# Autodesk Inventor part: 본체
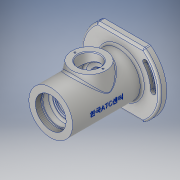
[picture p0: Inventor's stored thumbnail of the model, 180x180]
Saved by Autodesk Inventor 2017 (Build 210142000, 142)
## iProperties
Part Number: 본체
Material: 알루미늄 6061
Document SubType Name: Modeling
Designer: Administrator
Density: 2.7 g/cm^3
Appearance: 알루미늄 - 평지
Mass: 690.714 g
Surface Area: 618.652 cm^2
Volume: 255.82 cm^3
Author: Administrator
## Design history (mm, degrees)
sketch "스케치1"
  geometry: L1 (-33.985, 47)-(33.985, 47); L2 (33.985, 47)-(33.985, -47); L3 (33.985, -47)-(-33.985, -47); L4 (-33.985, -47)-(-33.985, 47); L5 (-33.985, 47)-(33.985, -47); L6 (33.985, 47)-(-33.985, -47); A1 r 58 centre (0, 0) between (-33.985, 47) and (-33.985, -47); A2 r 58 centre (0, 0) between (33.985, 47) and (-33.985, 47); A3 r 58 centre (0, 0) between (-33.985, -47) and (33.985, 47); 1 further point
  constraints: 12 end point, 8 point on circle, 3 centre point, 2 midpoint, 2 parallel, 1 coincident, 1 horizontal, 1 perpendicular
  dimensions: "d0" = 116 diameter of A1; "d1" = 94 distance of L3.end L1.start
extrude "돌출1" new body sketch "스케치1" distance "d2" = 10; taper "d3" = 0 deg
sketch "스케치2"
  geometry: C1 r 36 at (0, 0); 1 further point
  constraints: 1 centre point, 1 coincident
  dimensions: "d4" = 72 diameter of C1
extrude "돌출2" join sketch "스케치2" distance "d5" = 3; taper "d6" = 0 deg
sketch "스케치3"
  geometry: C1 r 32 at (0, 0); 1 further point
  constraints: 1 centre point, 1 coincident
  dimensions: "d7" = 64 diameter of C1
extrude "돌출3" join sketch "스케치3" distance "d8" = 102; taper "d9" = 0 deg
sketch "스케치4"
  geometry: L1 (0, 0)-(48, 0); L2 (0, 0)-(36.77, 30.854); L3 (-48, 0)-(0, 0); L4 (-36.77, -30.854)-(0, 0); C1 r 4 at (-36.77, -30.854); C2 r 4 at (36.77, 30.854); A1 r 48 centre (0, 0) between (48, 0) and (36.77, 30.854); A2 r 48 centre (0, 0) between (48, 0) and (36.77, 30.854); A3 r 48 centre (0, 0) between (-48, 0) and (-36.77, -30.854); 1 further point
  constraints: 8 end point, 8 point on circle, 5 centre point, 3 coincident, 2 concentric, 2 horizontal alignment
  dimensions: "d10" = 96 diameter of A1; "d11" = 40 deg angle of L1 L2; "d13" = 40 deg angle of L4 L3; "d15" = 8 diameter of C1; "d16" = 8 diameter of C2
extrude "돌출4" cut sketch "스케치4" distance "d17" = 10; taper "d18" = 0 deg
sketch "스케치5"
  geometry: L1 (-48, 0)-(48, 0); L2 (-36.77, -30.854)-(36.77, 30.854); C1 r 4 at (-36.77, -30.854) reference; C2 r 4 at (36.77, 30.854) reference; A1 r 48 centre (0, 0) between (-48, 0) and (48, 0); A2 r 48 centre (0, 0) between (48, 0) and (36.77, 30.854); A3 r 52 centre (0, 0) between (52, 0) and (39.834, 33.425); A4 r 44 centre (0, 0) between (44, 0) and (33.706, 28.283); A5 r 4 centre (48, 0) between (44, 0) and (52, 0); A6 r 4 centre (36.77, 30.854) between (39.834, 33.425) and (33.706, 28.283); A7 r 48 centre (0, 0) between (-48, 0) and (-36.77, -30.854); A8 r 52 centre (0, 0) between (-52, 0) and (-39.834, -33.425); A9 r 44 centre (0, 0) between (-44, 0) and (-33.706, -28.283); A10 r 4 centre (-48, 0) between (-44, 0) and (-52, 0); A11 r 4 centre (-36.77, -30.854) between (-39.834, -33.425) and (-33.706, -28.283); 2 further points
  constraints: 22 point on circle, 11 centre point, 8 tangent, 4 end point, 2 concentric, 2 horizontal alignment, 1 coincident, 1 horizontal, 1 midpoint
  dimensions: "d19" = 96 diameter of A1; "d20" = 8 diameter of A5; "d21" = 8 diameter of A10; "d22" = 30.85381 vertical distance of L2.start L1.start
extrude "돌출5" cut sketch "스케치5" distance "d23" = 4.4; taper "d24" = 0 deg
sketch "스케치6" dims "d25" = 96
  geometry: L1 (-36.77, -30.854)-(0, 0); L2 (0, 0)-(36.77, 30.854); L3 (0, 0)-(-48, 0); L4 (0, 0)-(48, 0); C1 r 4 at (-36.77, -30.854) reference; C2 r 4 at (36.77, 30.854) reference; A1 r 4 centre (48, 0) between (44, 0) and (52, 0) reference; A2 r 48 centre (0, 0) between (-48, 0) and (-36.77, -30.854); A3 r 50.25 centre (0, 0) between (-50.25, 0) and (-38.494, -32.3); A4 r 45.75 centre (0, 0) between (-45.75, 0) and (-35.047, -29.408); A5 r 2.25 centre (-48, 0) between (-45.75, 0) and (-50.25, 0); A6 r 2.25 centre (-36.77, -30.854) between (-38.494, -32.3) and (-35.047, -29.408); A7 r 48 centre (0, 0) between (48, 0) and (36.77, 30.854); A8 r 50.25 centre (0, 0) between (50.25, 0) and (38.494, 32.3); A9 r 45.75 centre (0, 0) between (45.75, 0) and (35.047, 29.408); A10 r 2.25 centre (48, 0) between (45.75, 0) and (50.25, 0); A11 r 2.25 centre (36.77, 30.854) between (38.494, 32.3) and (35.047, 29.408); 1 further point
  constraints: 20 point on circle, 10 centre point, 8 end point, 8 tangent, 2 horizontal, 1 coincident, 1 collinear, 1 concentric, 1 horizontal alignment, 3 other
  dimensions: "d26" = 4.5 diameter of A5; "d27" = 4.5 diameter of A10
extrude "돌출6" cut sketch "스케치6" distance "d28" = 10; taper "d29" = 0 deg
sketch "스케치7"
  geometry: L1 (32, 112)-(-32, 112) reference; L2 (0, 112)-(0, -3); L3 (-36, -3)-(36, -3) reference; L4 (0, 112)-(22.5, 112); L5 (22.5, 112)-(22.5, 104); L6 (22.5, 104)-(24, 104); L7 (24, 104)-(24, 101); L8 (24, 101)-(22.5, 101); L9 (22.5, 101)-(22.5, 90); L10 (22.5, 90)-(17.5, 90); L11 (17.5, 90)-(17.5, 88.25); L12 (17.5, 88.25)-(18.5, 88.25); L13 (18.5, 88.25)-(18.5, 86); L14 (18.5, 86)-(17.5, 86); L15 (17.5, 86)-(17.5, 75); L16 (17.5, 75)-(27, 75); L17 (27, 75)-(27, 37); L18 (27, 37)-(17.5, 37); L19 (17.5, 37)-(17.5, 26); L20 (17.5, 26)-(15, 26); L21 (15, 26)-(15, 21); L22 (15, 21)-(11, 21); L23 (11, 21)-(11, 18.3); L24 (11, 18.3)-(15, 18.3); L25 (15, 18.3)-(15, 11); L26 (15, 11)-(20, 11); L27 (20, 11)-(30, -3); 1 further point
  constraints: 50 end point, 19 perpendicular, 4 point on line, 2 midpoint, 1 horizontal, 1 vertical
  dimensions: "d30" = 45 diameter of L5 L2; "d31" = 48 diameter of L7 L2; "d32" = 45 diameter of L9 L2; "d33" = 35 diameter of L11 L2; "d34" = 37 diameter of L13 L2; "d35" = 54 diameter of L17 L2; "d36" = 35 diameter of L19 L2; "d37" = 30 diameter of L21 L2; "d38" = 22 diameter of L23 L2; "d39" = 30 diameter of L25 L2; "d41" = 40 diameter of L26.end L2; "d42" = 60 diameter of L27.end L2; "d43" = 8 distance of L4.end L5.end; "d44" = 3 distance of L6.end L7.end; "d45" = 22 distance between parallel lines of L10 L4; "d47" = 1.75 distance of L10.end L11.end; "d48" = 4 distance between parallel lines of L14 L10; "d49" = 11 distance of L14.end L15.end; "d50" = 38 distance of L16.end L17.end; "d51" = 11 distance of L18.end L19.end; "d52" = 5 distance of L20.end L21.end; "d53" = 14 distance between parallel lines of L3 L26; "d54" = 7.3 distance of L24.end L25.end
revolve "회전1" sketch "스케치7" stored, may be unused: angle "d55" = 90 deg
node "작업 평면1"
sketch "스케치8"
  geometry: L1 (32, 112)-(-32, 112) reference; C1 r 25 at (0, 56); 1 further point
  constraints: 1 centre point, 1 vertical alignment
  dimensions: "d57" = 50 diameter of C1; "d58" = 56 distance from line of C1.centre L1
extrude "돌출7" join sketch "스케치8" stored distance "d59" = 10; taper "d60" = 10 deg
sketch "스케치9"
  geometry: C1 r 25 at (0, 0) reference; C2 r 16 at (0, 0); 1 further point
  constraints: 1 centre point, 1 coincident
  dimensions: "d61" = 32 diameter of C2
extrude "돌출8" cut sketch "스케치9" distance "d62" = 35; taper "d63" = 0 deg
sketch "스케치10"
  geometry: C1 r 25 at (0, 0) reference; A1 r 20.5 centre (0, 0) between (-20.5, 0) and (20.5, 0); 1 further point
  constraints: 2 horizontal alignment, 2 point on circle, 1 centre point, 1 coincident
  dimensions: "d64" = 41 diameter of A1
hole "구멍1" sketch "스케치10" at (-20.5, 0), (20.5, 0) diameter "d65" = 2.459; stored, may be unused: countersink angle "d69" = 90 deg, drill point angle "d71" = 118 deg; dims "d66" = 6, "d67" = 4, "d68" = 2, "d70" = 8
node "작업 평면2"
sketch "스케치11"
  geometry: L1 (47, 0)-(-47, 0) reference; 3 further points
  constraints: 1 midpoint, 1 vertical alignment, 1 other
  dimensions: "d73" = 62 distance from line of L1 point (0, 62)
feature "엠보싱1" sketch "스케치11" dims "d74" = 0.5, "d75" = 0
fillet "모깎기1" dims "d76" = 3
fillet "모깎기2" dims "d77" = 3
fillet "모깎기3" dims "d78" = 3
fillet "모깎기4" dims "d79" = 3
chamfer "모따기1" distance "d80" = 1; stored, may be unused: second distance "d81" = 2, angle "d82" = 45 deg
feature "스레드1" dims "d83" = 10, "d84" = 0
chamfer "모따기2" distance "d85" = 1; stored, may be unused: second distance "d86" = 2, angle "d87" = 30 deg
sketch "스케치12"
  geometry: 1 further point
chamfer "모따기4" distance "d91" = 1; stored, may be unused: second distance "d92" = 2, angle "d93" = 30 deg
chamfer "모따기5" distance "d94" = 1; stored, may be unused: second distance "d95" = 2, angle "d96" = 30 deg
chamfer "모따기6" distance "d97" = 1; stored, may be unused: second distance "d98" = 2, angle "d99" = 30 deg
fillet "모깎기5" dims "d100" = 0.5
fillet "모깎기6" dims "d101" = 0.6
chamfer "모따기7" distance "d102" = 0.7; stored, may be unused: second distance "d103" = 2, angle "d104" = 30 deg
node "솔리드1"
other parameters: "d56" = 38, "d72" = 42
